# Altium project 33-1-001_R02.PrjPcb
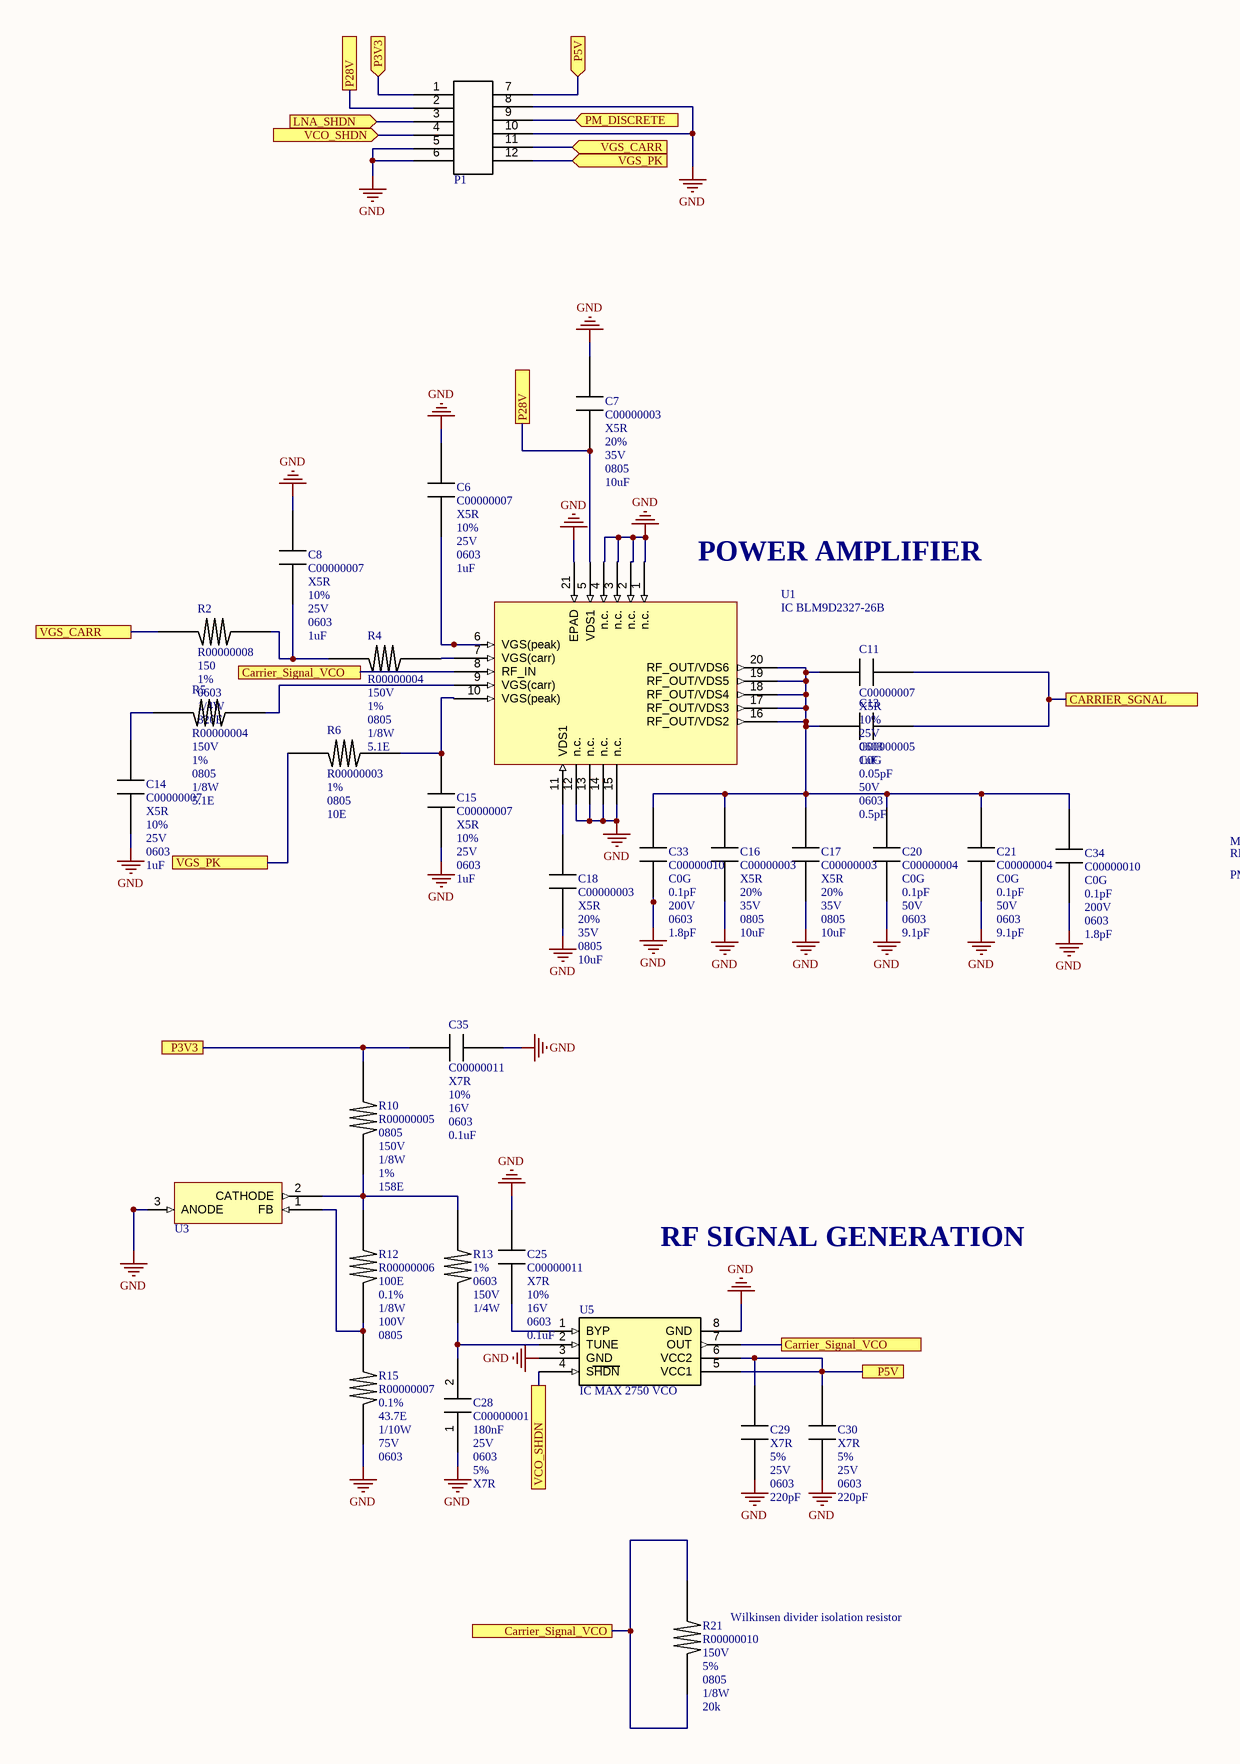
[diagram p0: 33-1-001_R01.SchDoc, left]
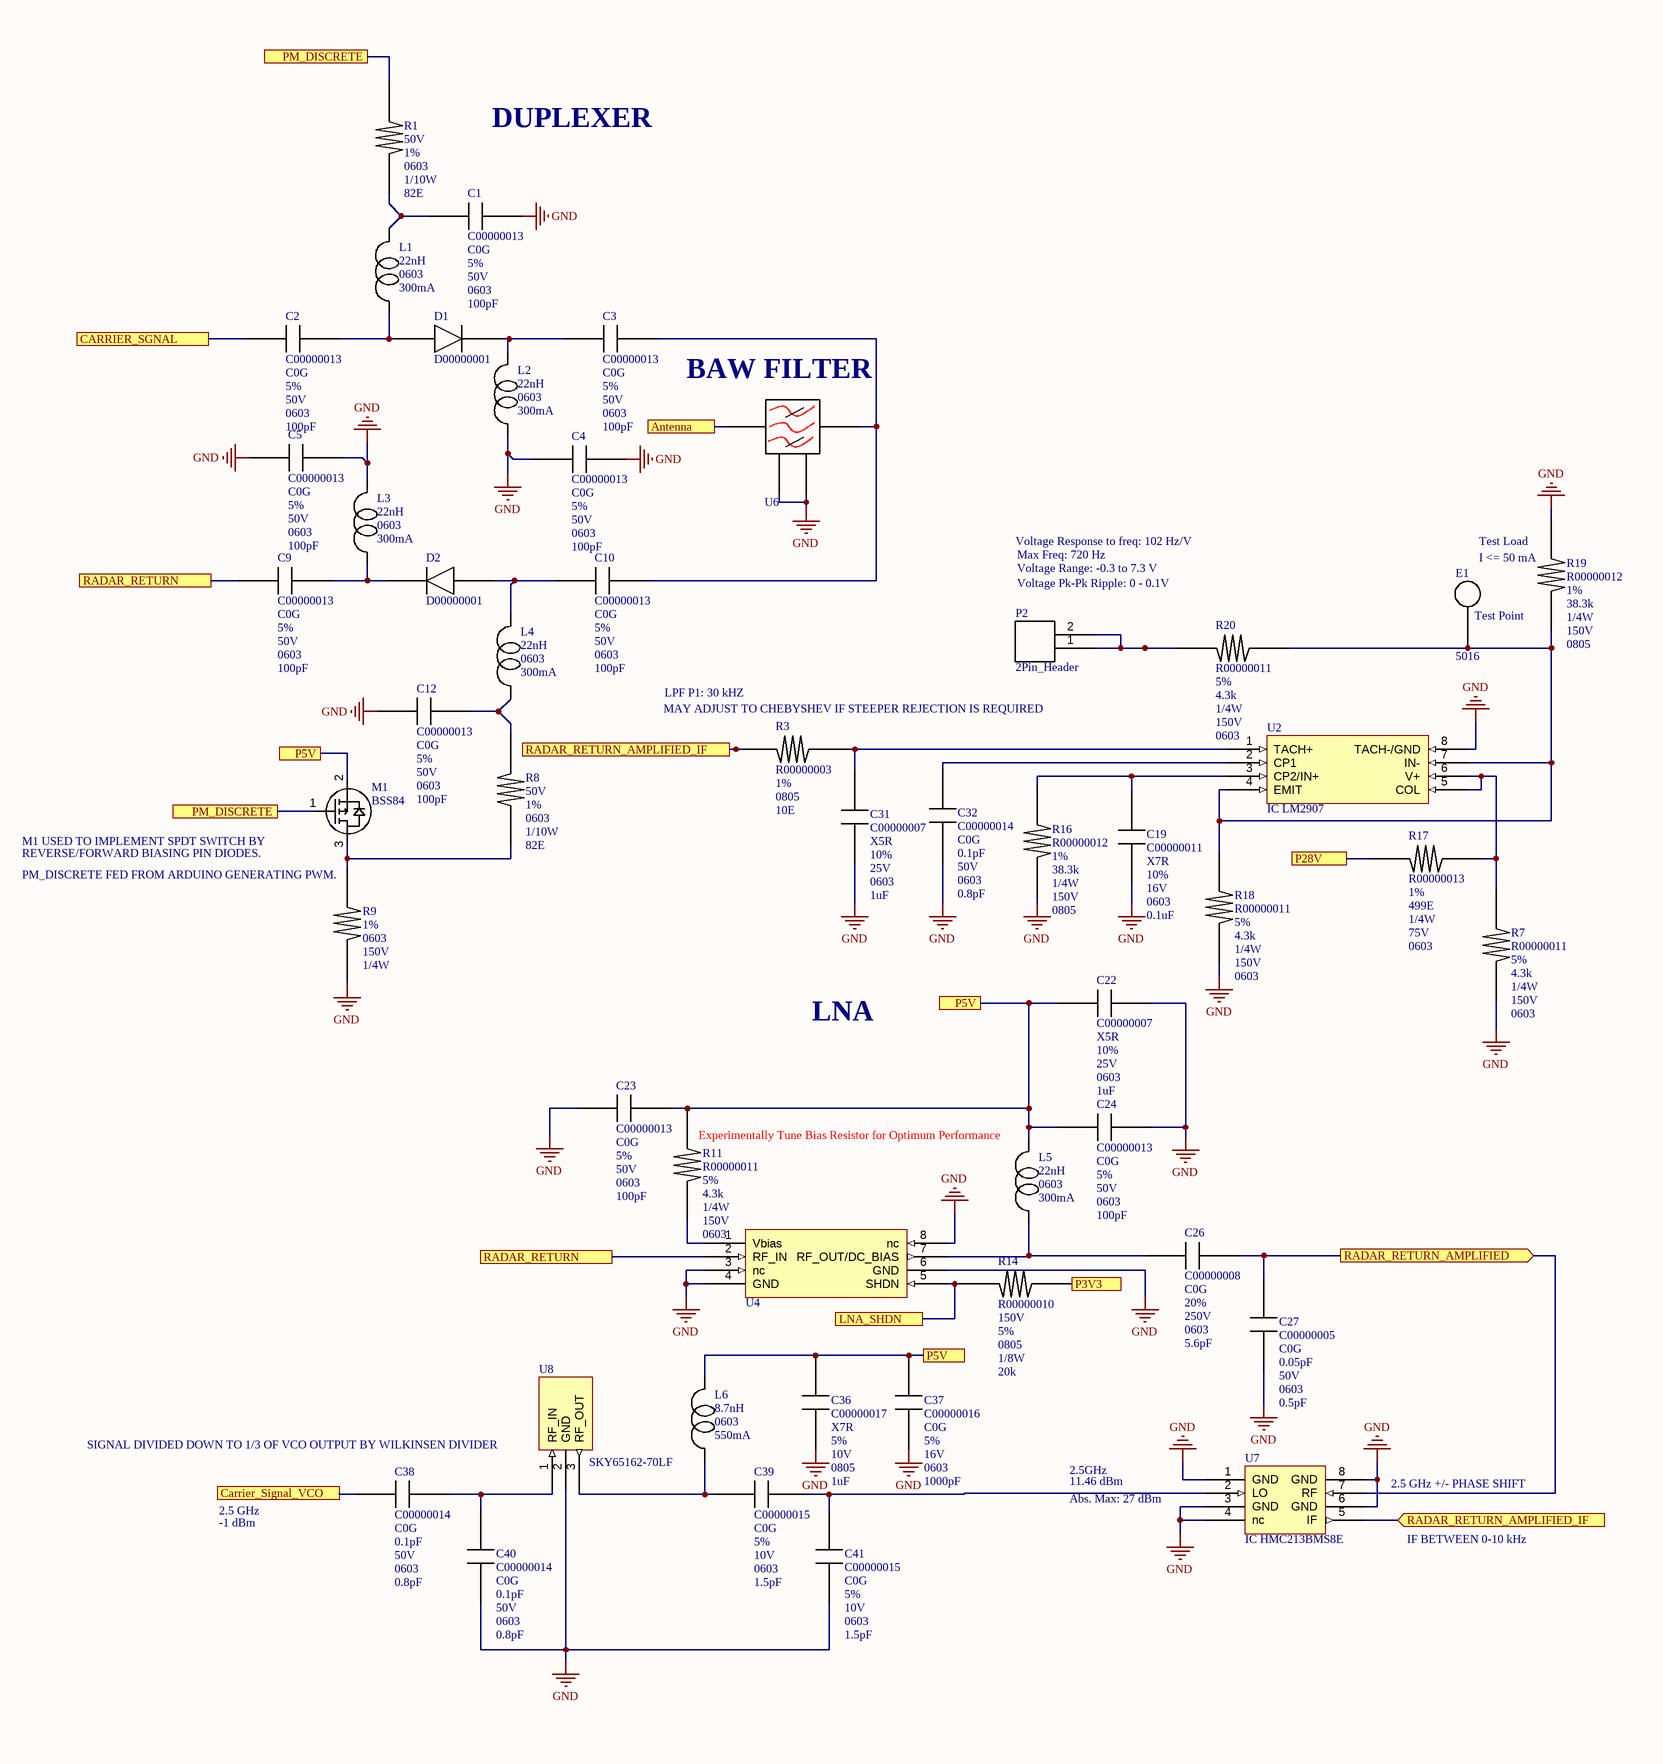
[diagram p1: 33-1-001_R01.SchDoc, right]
1 sheet, 82 parts. Net scope: flat (ports and power ports of the same name join across sheets).
Board file: PCB1.PcbDoc

## Sheet 33-1-001_R01.SchDoc: RF Module
size 558 x 431 mm; Date: 10/26/2021; ApprovedBy: G. Mays; CheckedBy: J. Lusher; Author: G. Mays; CompanyName: Team 33; DrawnBy: G. Mays; Engineer: G. Mays; Organization: Texas A&M; DocumentNumber: 33-1-001; Revision: 01; SheetNumber: 1; SheetTotal: 1

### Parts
C1  C00000013  Dielectric: C0G  Tolerance: 5%  Voltage: 50V  Package: 0603  Capacitance: 100pF  [C0603C101J5GAC7082]
C2  C00000013  Dielectric: C0G  Tolerance: 5%  Voltage: 50V  Package: 0603  Capacitance: 100pF  [C0603C101J5GAC7082]
C3  C00000013  Dielectric: C0G  Tolerance: 5%  Voltage: 50V  Package: 0603  Capacitance: 100pF  [C0603C101J5GAC7082]
C4  C00000013  Dielectric: C0G  Tolerance: 5%  Voltage: 50V  Package: 0603  Capacitance: 100pF  [C0603C101J5GAC7082]
C5  C00000013  Dielectric: C0G  Tolerance: 5%  Voltage: 50V  Package: 0603  Capacitance: 100pF  [C0603C101J5GAC7082]
C6  C00000007  Dielectric: X5R  Tolerance: 10%  Voltage: 25V  Package: 0603  Capacitance: 1uF  [06033D105KAT2A]
C7  C00000003  Dielectric: X5R  Tolerance: 20%  Voltage: 35V  Package: 0805  Capacitance: 10uF  [C2012X5R1V106K125AC]
C8  C00000007  Dielectric: X5R  Tolerance: 10%  Voltage: 25V  Package: 0603  Capacitance: 1uF  [06033D105KAT2A]
C9  C00000013  Dielectric: C0G  Tolerance: 5%  Voltage: 50V  Package: 0603  Capacitance: 100pF  [C0603C101J5GAC7082]
C10  C00000013  Dielectric: C0G  Tolerance: 5%  Voltage: 50V  Package: 0603  Capacitance: 100pF  [C0603C101J5GAC7082]
C11  C00000007  Dielectric: X5R  Tolerance: 10%  Voltage: 25V  Package: 0603  Capacitance: 1uF  [06033D105KAT2A]
C12  C00000013  Dielectric: C0G  Tolerance: 5%  Voltage: 50V  Package: 0603  Capacitance: 100pF  [C0603C101J5GAC7082]
C13  C00000005  Dielectric: C0G  Tolerance: 0.05pF  Voltage: 50V  Package: 0603  Capacitance: 0.5pF  [CBR06C508A5GAC]
C14  C00000007  Dielectric: X5R  Tolerance: 10%  Voltage: 25V  Package: 0603  Capacitance: 1uF  [06033D105KAT2A]
C15  C00000007  Dielectric: X5R  Tolerance: 10%  Voltage: 25V  Package: 0603  Capacitance: 1uF  [06033D105KAT2A]
C16  C00000003  Dielectric: X5R  Tolerance: 20%  Voltage: 35V  Package: 0805  Capacitance: 10uF  [C2012X5R1V106K125AC]
C17  C00000003  Dielectric: X5R  Tolerance: 20%  Voltage: 35V  Package: 0805  Capacitance: 10uF  [C2012X5R1V106K125AC]
C18  C00000003  Dielectric: X5R  Tolerance: 20%  Voltage: 35V  Package: 0805  Capacitance: 10uF  [C2012X5R1V106K125AC]
C19  C00000011  Dielectric: X7R  Tolerance: 10%  Voltage: 16V  Package: 0603  Capacitance: 0.1uF  [C0603C104K4RACTU]
C20  C00000004  Dielectric: C0G  Tolerance: 0.1pF  Voltage: 50V  Package: 0603  Capacitance: 9.1pF  [06035U9R1BAT2A]
C21  C00000004  Dielectric: C0G  Tolerance: 0.1pF  Voltage: 50V  Package: 0603  Capacitance: 9.1pF  [06035U9R1BAT2A]
C22  C00000007  Dielectric: X5R  Tolerance: 10%  Voltage: 25V  Package: 0603  Capacitance: 1uF  [06033D105KAT2A]
C23  C00000013  Dielectric: C0G  Tolerance: 5%  Voltage: 50V  Package: 0603  Capacitance: 100pF  [C0603C101J5GAC7082]
C24  C00000013  Dielectric: C0G  Tolerance: 5%  Voltage: 50V  Package: 0603  Capacitance: 100pF  [C0603C101J5GAC7082]
C25  C00000011  Dielectric: X7R  Tolerance: 10%  Voltage: 16V  Package: 0603  Capacitance: 0.1uF  [C0603C104K4RACTU]
C26  C00000008  Dielectric: C0G  Tolerance: 20%  Voltage: 250V  Package: 0603  Capacitance: 5.6pF  [GQM1875C2E1R6BB12D]
C27  C00000005  Dielectric: C0G  Tolerance: 0.05pF  Voltage: 50V  Package: 0603  Capacitance: 0.5pF  [CBR06C508A5GAC]
C28  C00000001  Capacitance: 180nF  Voltage: 25V  Package: 0603  Tolerance: 5%  Dielectric: X7R  [C0603C184J3RACTU]
C29  Dielectric: X7R  Tolerance: 5%  Voltage: 25V  Package: 0603  Capacitance: 220pF  [C0603C221J3RACAUTO]  (hidden comment: C00000012)
C30  Dielectric: X7R  Tolerance: 5%  Voltage: 25V  Package: 0603  Capacitance: 220pF  [C0603C221J3RACAUTO]  (hidden comment: C00000012)
C31  C00000007  Dielectric: X5R  Tolerance: 10%  Voltage: 25V  Package: 0603  Capacitance: 1uF  [06033D105KAT2A]
C32  C00000014  Dielectric: C0G  Tolerance: 0.1pF  Voltage: 50V  Package: 0603  Capacitance: 0.8pF  [ML03510R8BAT2A]
C33  C00000010  Dielectric: C0G  Tolerance: 0.1pF  Voltage: 200V  Package: 0603  Capacitance: 1.8pF  [VJ0603D1R8BXCQJHT]
C34  C00000010  Dielectric: C0G  Tolerance: 0.1pF  Voltage: 200V  Package: 0603  Capacitance: 1.8pF  [VJ0603D1R8BXCQJHT]
C35  C00000011  Dielectric: X7R  Tolerance: 10%  Voltage: 16V  Package: 0603  Capacitance: 0.1uF  [C0603C104K4RACTU]
C36  C00000017  Dielectric: X7R  Tolerance: 5%  Voltage: 10V  Package: 0805  Capacitance: 1uF  [EMK212B7105KG-T]
C37  C00000016  Dielectric: C0G  Tolerance: 5%  Voltage: 16V  Package: 0603  Capacitance: 1000pF  [C0603C102F4GACTU]
C38  C00000014  Dielectric: C0G  Tolerance: 0.1pF  Voltage: 50V  Package: 0603  Capacitance: 0.8pF  [ML03510R8BAT2A]
C39  C00000015  Dielectric: C0G  Tolerance: 5%  Voltage: 10V  Package: 0603  Capacitance: 1.5pF  [VJ0603A1R5CXQCW1BC]
C40  C00000014  Dielectric: C0G  Tolerance: 0.1pF  Voltage: 50V  Package: 0603  Capacitance: 0.8pF  [ML03510R8BAT2A]
C41  C00000015  Dielectric: C0G  Tolerance: 5%  Voltage: 10V  Package: 0603  Capacitance: 1.5pF  [VJ0603A1R5CXQCW1BC]
D1  D00000001  [SMP1334-084LF]
D2  D00000001  [SMP1334-084LF]
E1  5016  [5016]
L1  Inductance: 22nH  Package: 0603  Imax: 300mA  [ILC0603ER22NJ]  (hidden comment: L00000001)
L2  Inductance: 22nH  Package: 0603  Imax: 300mA  [ILC0603ER22NJ]  (hidden comment: L00000001)
L3  Inductance: 22nH  Package: 0603  Imax: 300mA  [ILC0603ER22NJ]  (hidden comment: L00000001)
L4  Inductance: 22nH  Package: 0603  Imax: 300mA  [ILC0603ER22NJ]  (hidden comment: L00000001)
L5  Inductance: 22nH  Package: 0603  Imax: 300mA  [ILC0603ER22NJ]  (hidden comment: L00000001)
L6  Inductance: 8.7nH  Package: 0603  Imax: 550mA  [LQW18AS8N7J00D]  (hidden comment: L00000002)
M1  BSS84  [BSS84,215]
P1  67997-112HLF  [67997-112HLF]  (value not drawn)
P2  2Pin_Header  [2Pin_Header]
R1  Voltage Rating: 50V  Tolerance: 1%  Package: 0603  Power: 1/10W  Resistance: 82E  [CR0603-JW-820ELF]  (hidden comment: R00000009)
R2  R00000008  Voltage Rating: 150  Tolerance: 1%  Package: 0603  Power: 1/4W  Resistance: 820E  [ERJ-U3RD8200V]
R3  R00000003  Tolerance: 1%  Package: 0805  Resistance: 10E  [SFR10EZPF10R0]
R4  R00000004  Voltage Rating: 150V  Tolerance: 1%  Package: 0805  Power: 1/8W  Resistance: 5.1E  [CRCW08055R10FKTA]
R5  R00000004  Voltage Rating: 150V  Tolerance: 1%  Package: 0805  Power: 1/8W  Resistance: 5.1E  [CRCW08055R10FKTA]
R6  R00000003  Tolerance: 1%  Package: 0805  Resistance: 10E  [SFR10EZPF10R0]
R7  R00000011  Tolerance: 5%  Resistance: 4.3k  Power: 1/4W  Voltage Rating: 150V  Package: 0603  [ESR03EZPJ432]
R8  Voltage Rating: 50V  Tolerance: 1%  Package: 0603  Power: 1/10W  Resistance: 82E  [CR0603-JW-820ELF]  (hidden comment: R00000009)
R9  Tolerance: 1%  Package: 0603  Voltage Rating: 150V  Power: 1/4W  [ERJ-UP3F8660V]  (hidden comment: R00000001)
R10  R00000005  Package: 0805  Voltage Rating: 150V  Power: 1/8W  Tolerance: 1%  Resistance: 158E  [CR0805-FX-1580ELF]
R11  R00000011  Tolerance: 5%  Resistance: 4.3k  Power: 1/4W  Voltage Rating: 150V  Package: 0603  [ESR03EZPJ432]
R12  R00000006  Resistance: 100E  Tolerance: 0.1%  Power: 1/8W  Voltage Rating: 100V  Package: 0805  [ERA-6AEB101V]
R13  Tolerance: 1%  Package: 0603  Voltage Rating: 150V  Power: 1/4W  [ERJ-UP3F8660V]  (hidden comment: R00000001)
R14  R00000010  Voltage Rating: 150V  Tolerance: 5%  Package: 0805  Power: 1/8W  Resistance: 20k  [CR0805-JW-203ELF]
R15  R00000007  Tolerance: 0.1%  Resistance: 43.7E  Power: 1/10W  Voltage Rating: 75V  Package: 0603  [RN73H1JTTD43R7B25 - duplicate]
R16  R00000012  Tolerance: 1%  Resistance: 38.3k  Power: 1/4W  Voltage Rating: 150V  Package: 0805  [RK73H2ATTD3832F]
R17  R00000013  Tolerance: 1%  Resistance: 499E  Power: 1/4W  Voltage Rating: 75V  Package: 0603  [RCS0603499RFKEA]
R18  R00000011  Tolerance: 5%  Resistance: 4.3k  Power: 1/4W  Voltage Rating: 150V  Package: 0603  [ESR03EZPJ432]
R19  R00000012  Tolerance: 1%  Resistance: 38.3k  Power: 1/4W  Voltage Rating: 150V  Package: 0805  [RK73H2ATTD3832F]
R20  R00000011  Tolerance: 5%  Resistance: 4.3k  Power: 1/4W  Voltage Rating: 150V  Package: 0603  [ESR03EZPJ432]
R21  R00000010  Voltage Rating: 150V  Tolerance: 5%  Package: 0805  Power: 1/8W  Resistance: 20k  [CR0805-JW-203ELF]
U1  IC BLM9D2327-26B  [BLM9D2327-26B]
U2  IC LM2907  [LM2907]
U3  IC TL4051AQDBZR  [TL4051AQDBZR]  (value not drawn)
U4  IC QPL9503  [QPL9503]  (value not drawn)
U5  IC MAX 2750 VCO  [MAX2750EUA+]
U6  DEA162495BT-1289A1  [DEA162495BT-1289A1]  (value not drawn)
U7  IC HMC213BMS8E  [HMC213BMS8E]
U8  SKY65162-70LF  [SKY65162-70LF]

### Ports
Antenna, CARRIER_SGNAL, Carrier_Signal_VCO, LNA_SHDN, LNA_SHDN (in), P3V3, P3V3 (in), P5V, P5V (in), P28V, PM_DISCRETE, PM_DISCRETE (in), RADAR_RETURN, RADAR_RETURN_AMPLIFIED (out), RADAR_RETURN_AMPLIFIED_IF, RADAR_RETURN_AMPLIFIED_IF (in), VCO_SHDN, VCO_SHDN (in), VGS_CARR, VGS_CARR (in), VGS_PK, VGS_PK (in)

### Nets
GND: C1.2 C4.1 C4.2 C5.1 C5.2 C6.2 C7.2 C8.2 C12.2 C14.1 C15.1 C16.1 C17.1 C18.1 C19.1 C20.1 C21.1 C22.1 C23.1 C24.2 C25.2 C27.1 C28.1 C29.1 C30.1 C31.1 C32.1 C33.1 C34.1 C35.1 C36.1 C37.1 C40.1 C41.1 L2.1 L3.2 P1.5 P1.6 P1.8 P1.10 R7.1 R9.1 R15.1 R16.1 R18.1 R19.2 U1.1(n.c.) U1.2(n.c.) U1.3(n.c.) U1.4(n.c.) U1.12(n.c.) U1.13(n.c.) U1.14(n.c.) U1.15(n.c.) U1.21(EPAD) U2.8(TACH-/GND) U3.3(ANODE) U4.3(nc) U4.4(GND) U4.6(GND) U4.8(nc) U5.3(GND) U5.8(GND) U6.2 U6.4 U7.1(GND) U7.3(GND) U7.4(nc) U7.6(GND) U7.8(GND) U8.2(GND)
NetC1_1: C1.1 L1.2 R1.1
NetC2_1: C2.1 C11.1 C13.2 ; port CARRIER_SGNAL
NetC2_2: C2.2 D1.2 L1.1
NetC3_1: C3.1 D1.1 L2.2
NetC3_2: C3.2 C10.2 U6.3
NetC6_1: C6.1 U1.6(VGS(peak))
NetC7_1: C7.1 P1.2 R17.1 U1.5(VDS1) ; port P28V
NetC8_1: C8.1 R2.2 R4.1
NetC9_1: C9.1 U4.2(RF_IN) ; port RADAR_RETURN
NetC9_2: C9.2 D2.1 L3.1
NetC10_1: C10.1 D2.2 L4.2
NetC11_2: C11.2 C13.1 C16.2 C17.2 C20.2 C21.2 C33.2 C34.2 U1.16(RF_OUT/VDS2) U1.17(RF_OUT/VDS3) U1.18(RF_OUT/VDS4) U1.19(RF_OUT/VDS5) U1.20(RF_OUT/VDS6)
NetC12_1: C12.1 L4.1 R8.1
NetC14_2: C14.2 R5.1
NetC15_2: C15.2 R6.2 U1.10(VGS(peak))
NetC18_2: C18.2 U1.11(VDS1)
NetC19_2: C19.2 R16.2 U2.3(CP2/IN+)
NetC22_2: C22.2 C23.2 C24.1 C29.2 C30.2 C36.2 C37.2 L5.2 L6.2 M1.2 P1.7 R11.2 U5.5(VCC1) U5.6(VCC2) ; port P5V
NetC25_1: C25.1 U5.1(BYP)
NetC26_1: C26.1 L5.1 U4.7(RF_OUT/DC_BIAS)
NetC26_2: C26.2 C27.2 U7.7(RF) ; port RADAR_RETURN_AMPLIFIED
NetC28_2: C28.2 R13.1 U5.2(TUNE)
NetC31_2: C31.2 R3.2 U2.1(TACH+)
NetC32_2: C32.2 U2.2(CP1)
NetC35_2: C35.2 P1.1 R10.2 R14.2 ; port P3V3
NetC38_1: C38.1 R21.1 R21.2 U1.8(RF_IN) U5.7(OUT) ; port Carrier_Signal_VCO
NetC38_2: C38.2 C40.2 U8.1(RF_IN)
NetC39_1: C39.1 L6.1 U8.3(RF_OUT)
NetC39_2: C39.2 C41.2 U7.2(LO)
NetE1_1: E1.1 R18.2 R19.1 R20.2 U2.4(EMIT) U2.7(IN-)
NetM1_1: M1.1 P1.9 R1.2 ; port PM_DISCRETE
NetM1_3: M1.3 R8.2 R9.2
NetP1_3: P1.3 R14.1 U4.5(SHDN) ; port LNA_SHDN
NetP1_4: P1.4 U5.4(SHDN) ; port VCO_SHDN
NetP1_11: P1.11 R2.1 ; port VGS_CARR
NetP1_12: P1.12 R6.1 ; port VGS_PK
NetP2_1: P2.1 P2.2 R20.1
NetR3_1: R3.1 U7.5(IF) ; port RADAR_RETURN_AMPLIFIED_IF
NetR4_2: R4.2 U1.7(VGS(carr))
NetR5_2: R5.2 U1.9(VGS(carr))
NetR7_2: R7.2 R17.2 U2.5(COL) U2.6(V+)
NetR10_1: R10.1 R12.2 R13.2 U3.2(CATHODE)
NetR11_1: R11.1 U4.1(Vbias)
NetR12_1: R12.1 R15.2 U3.1(FB)
NetU6_1: U6.1 ; port Antenna

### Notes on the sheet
- DUPLEXER
- (near U6) BAW FILTER
- (near U1) POWER AMPLIFIER
- Voltage Response to freq: 102 Hz/V
- Max Freq: 720 Hz
- (near R19) Test Load
- (near R19) I <= 50 mA
- Voltage Range: -0.3 to 7.3 V
- Voltage Pk-Pk Ripple: 0 - 0.1V
- (near E1) Test Point
- LPF P1: 30 kHZ
- (near R3) MAY ADJUST TO CHEBYSHEV IF STEEPER REJECTION IS REQUIRED
- M1 USED TO IMPLEMENT SPDT SWITCH BY
- REVERSE/FORWARD BIASING PIN DIODES.
- PM_DISCRETE FED FROM ARDUINO GENERATING PWM.
- LNA
- Experimentally Tune Bias Resistor for Optimum Performance
- RF SIGNAL GENERATION
- (near C38) SIGNAL DIVIDED DOWN TO 1/3 OF VCO OUTPUT BY WILKINSEN DIVIDER
- 11.46 dBm
- 2.5GHz
- Abs. Max: 27 dBm
- 2.5 GHz +/- PHASE SHIFT
- 2.5 GHz
- -1 dBm
- IF BETWEEN 0-10 kHz
- (near R21) Wilkinsen divider isolation resistor

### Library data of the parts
C1-C5 C9 C10 C12 C23 C24 = C00000013: MLCC 100pF 5% 50V 0603
C6 C8 C11 C14 C15 C22 C31 = C00000007: MLCC 1uF 25V X5R 0603
C7 C16-C18 = C00000003: MLCC 10uF 35V X5R 0805
C13 C27 = C00000005: MLCC 0.5pF 50V 0603 C0G
C19 C25 C35 = C00000011: MLCC 0.1uF 16V 0603 X7R
C20 C21 = C00000004: MLCC 9.1pF 50V 0603 C0G
C26 = C00000008: MLCC 5.6pF 250V C0G 0603
C28 = C00000001: MLCC 180nF 25V X7R 0603
C29 C30 = C00000012: MLCC 220pF 5% 25V 0603 X7R
C32 C38 C40 = C00000014: Capacitors MLCC - SMD/SMT 50V 0.8pF C0G 0603 0.1pF
C33 C34 = C00000010: MLCC 1.8 pF 250V C0G 0603
C36 = C00000017: MLCC - SMD/SMT 10V 1uF X7R 0805 10% / RoHS Compliant
C37 = C00000016: MLCC - SMD/SMT 16V 1000pF 0603 C0G 0.01
C39 C41 = C00000015: MLCC - SMD/SMT 0603 1.5pF 10volts C0G +/-0.25p
D1 D2 = D00000001: PIN DIODE .45 Pf .45 OHM .37 nH, 1-8GHz, SMP1334-084LF
E1 = 5016: SMD test point
L1-L5 = L00000001: 22nH 300mA 0603 RF Inductor
L6 = L00000002: IND 8.7nH 550mA 0603
M1 = BSS84: MOSFET P-CH DMOS 50V 130MA
R1 R8 = R00000009: RES CHIP 82E 5% 1/10W
R2 = R00000008: RES CHIP 820E 1%
R3 R6 = R00000003: RES CHIP 10E 0805 1%
R4 R5 = R00000004: RES CHIP 5.1E 0805 1%
R7 R11 R18 R20 = R00000011: RES CHIP 4.3k 5% 0603 ESR03EZPJ432
R9 R13 = R00000001: RES CHIP 866 0603 1%; Resistance: 866E
R10 = R00000005: RES CHIP 158E 0805 1%
R12 = R00000006: RES CHIP 100E 0.1%
R14 R21 = R00000010: RES CHIP 20k 5% / CR0805-JW-203ELF
R15 = R00000007: RES CHIP 43.7E 0603 0.1%
R16 R19 = R00000012: RES CHIP 38.3k 1% 0805
R17 = R00000013: RES CHIP 499E 1% 0603 75V
U1 = IC BLM9D2327-26B: LDMOS 2-stage integrated Doherty MMIC
U3 = IC TL4051AQDBZR: Precision voltage reference
U5 = IC MAX 2750 VCO: 2.4-2.5 GHz VCO
U6 = DEA162495BT-1289A1: 2.5GHz BPF
U8 = SKY65162-70LF: SKY65162-70LF: 400 to 3800 MHz Linear Power Amplifier.; Gain: 13dB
